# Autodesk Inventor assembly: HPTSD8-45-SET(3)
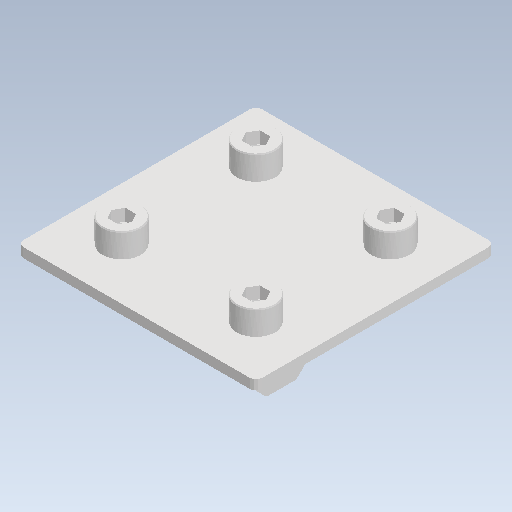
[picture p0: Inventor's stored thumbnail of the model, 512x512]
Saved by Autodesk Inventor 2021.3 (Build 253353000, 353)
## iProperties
Created: 2022-02
Part Number: HPTSD8-45-SET(3)
Document SubType Name: Assembly
Designer: kengo
Author: kengo
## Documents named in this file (4)
- C:\Users\kengo\Documents\S2S_frame\SDC345\frame_misumi_ver12\HPTSD8-45-SET(3).iam
- C:\Users\kengo\Documents\S2S_frame\SDC345\frame_misumi_ver12\HPTSD8-45.ipt
- C:\Users\kengo\Documents\S2S_frame\SDC345\frame_misumi_ver12\HNTT8-8.ipt
- C:\Users\kengo\Documents\S2S_frame\SDC345\frame_misumi_ver12\CBM8-15.ipt
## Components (9 placed, 3 different names)
1. HPTSD8-45
2. HNTT8-8
3. CBM8-15
4. HNTT8-8:1
5. CBM8-15:1
6. HNTT8-8:2
7. CBM8-15:2
8. HNTT8-8:3
9. CBM8-15:3
